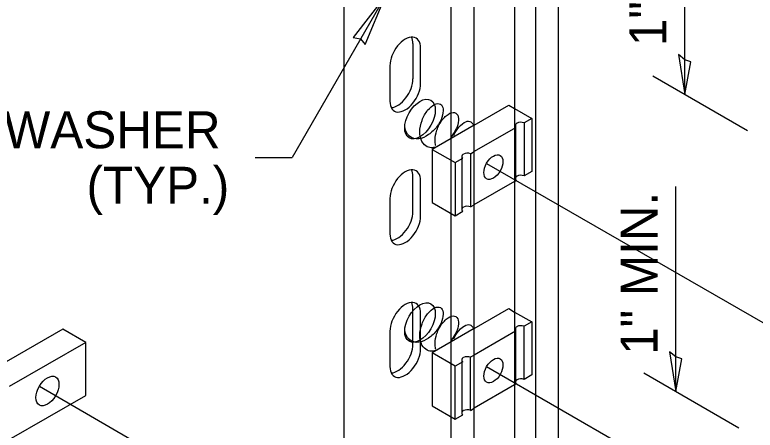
# Model space of a CAD drawing. Extents: x 99862 to 103151, y 100000 to 102076.
# Drawn here: x 101759.1 to 102079.7, y 100510.9 to 100690.6 of the extents above; entities that cross this region are included whole.
import ezdxf

# ---------------------------------------------------------------- set-up
doc = ezdxf.new("R2010")
doc.units = 0
for name, color, linetype in [('Level 1', 7, 'Continuous'), ('Level 15', 7, 'Continuous'), ('Level 16', 7, 'Continuous'), ('Level 20', 7, 'Continuous'), ('Level 3', 7, 'Continuous'), ('Level 7', 7, 'Continuous'), ('Level 8', 7, 'Continuous')]:
    doc.layers.add(name, color=color, linetype=linetype)

msp = doc.modelspace()

# ---------------------------------------------------------------- linework, layer by layer
at = {"layer": 'Level 1'}
for p, q in [((101901.65, 100836.31), (101901.65, 100346.41)), ((101975.53, 100836.31), (101975.53, 100342.05)), ((101994.46, 100342.6), (101994.46, 100836.31)), ((101984.51, 100830.57), (101984.51, 100336.86)), ((101958, 100325.36), (101958, 100815.26)), ((101948.05, 100319.62), (101948.05, 100809.52)), ((101931.48, 100678.14), (101931.48, 100662.83)), ((101934.8, 100660.91), (101934.8, 100676.22)), ((101921.54, 100668.57), (101921.54, 100653.26)), ((101931.48, 100605.42), (101931.48, 100620.73)), ((101934.8, 100603.5), (101934.8, 100618.81)), ((101921.54, 100611.16), (101921.54, 100595.85)), ((101931.48, 100548.01), (101931.48, 100563.32)), ((101934.8, 100546.09), (101934.8, 100561.4)), ((101921.54, 100553.75), (101921.54, 100538.44))]:
    msp.add_line(p, q, dxfattribs=at)
for centre, major_axis, start_param, end_param in [((101928.17, 100672.39), (4.69, 8.12), 5.497787, 8.63938), ((101924.85, 100674.31), (-4.69, -8.12), 2.356194, 2.780226), ((101928.17, 100657.08), (4.69, 8.12), 2.356194, 5.497787), ((101924.85, 100659), (-4.69, -8.12), 0.361367, 2.356194), ((101928.17, 100614.98), (4.69, 8.12), 5.497787, 8.63938), ((101924.85, 100616.9), (-4.69, -8.12), 2.356194, 2.780226), ((101924.85, 100601.59), (-4.69, -8.12), 0.361367, 2.356194), ((101928.17, 100599.68), (4.69, 8.12), 2.356194, 5.497787), ((101928.17, 100557.57), (4.69, 8.12), 5.497787, 8.63938), ((101924.85, 100559.49), (-4.69, -8.12), 2.356194, 2.780226), ((101924.85, 100544.18), (-4.69, -8.12), 0.361367, 2.356194), ((101928.17, 100542.27), (4.69, 8.12), 2.356194, 5.497787)]:
    msp.add_ellipse(centre, major_axis=major_axis, ratio=0.57735, start_param=start_param, end_param=end_param, dxfattribs=at)
at = {"layer": 'Level 15'}
for p, q in [((102049.16, 100656.1), (102049.16, 100716.68)), ((101919.66, 100698.98), (101879.16, 100628.84)), ((102076.42, 100640.36), (102035.3, 100664.1)), ((101863.16, 100628.84), (101879.16, 100628.84)), ((102045.28, 100527.56), (102045.28, 100616.32)), ((102072.54, 100511.81), (102031.42, 100535.56))]:
    msp.add_line(p, q, dxfattribs=at)
for points in [[(101919.66, 100698.98), (101905.66, 100680.71), (101908.77, 100680.13), (101910.83, 100677.72)], [(102049.16, 100656.1), (102051.83, 100670.29), (102049.16, 100671.1), (102046.49, 100673.37)], [(102045.28, 100527.56), (102047.95, 100541.74), (102045.28, 100542.56), (102042.61, 100544.83)]]:
    msp.add_lwpolyline(points, close=True, dxfattribs=at)
at = {"layer": 'Level 16'}
for p, q in [((101963.34, 100626.27), (102083.04, 100557.41)), ((101963.42, 100538.38), (102084.58, 100468.49)), ((101769.77, 100529.86), (101819.79, 100500.99))]:
    msp.add_line(p, q, dxfattribs=at)
at = {"layer": 'Level 3'}
for p, q in [((101958, 100642.86), (101972.98, 100651.51)), ((101972.98, 100651.51), (101975.53, 100650.03)), ((101975.53, 100650.03), (101982.92, 100645.77)), ((101976.59, 100643.72), (101976.53, 100643.68)), ((101982.92, 100645.77), (101979.61, 100643.85)), ((101979.61, 100643.85), (101979.61, 100620.89)), ((101982.92, 100645.77), (101982.92, 100622.8)), ((101958, 100642.86), (101939.83, 100632.37)), ((101975.85, 100641.68), (101958, 100631.38)), ((101975.85, 100642.73), (101975.85, 100619.76)), ((101939.83, 100632.37), (101939.83, 100609.41)), ((101939.83, 100632.37), (101949.78, 100626.63)), ((101956.41, 100630.46), (101958, 100631.38)), ((101949.78, 100626.63), (101953.09, 100628.54)), ((101952.65, 100629.33), (101952.65, 100606.37)), ((101953.39, 100630.32), (101953.33, 100630.28)), ((101953.33, 100630.28), (101953.39, 100630.32)), ((101956.41, 100630.46), (101956.41, 100607.49)), ((101949.78, 100626.63), (101949.78, 100603.66)), ((101982.92, 100622.8), (101979.61, 100620.89)), ((101975.53, 100618.53), (101957.93, 100608.37)), ((101975.53, 100618.53), (101976.29, 100618.97)), ((101976.59, 100620.75), (101976.53, 100620.71)), ((101939.83, 100609.41), (101949.78, 100603.66)), ((101949.78, 100603.66), (101953.09, 100605.58)), ((101953.39, 100607.36), (101953.33, 100607.32)), ((101953.33, 100607.32), (101953.39, 100607.36)), ((101956.41, 100607.49), (101958, 100608.41)), ((101958, 100554.83), (101972.98, 100563.48)), ((101972.98, 100563.48), (101975.53, 100562)), ((101975.53, 100562), (101982.92, 100557.74)), ((101982.92, 100557.74), (101979.61, 100555.82)), ((101982.92, 100557.74), (101982.92, 100534.77)), ((101958, 100554.83), (101939.83, 100544.34)), ((101975.85, 100554.7), (101975.85, 100531.74)), ((101976.59, 100555.69), (101976.53, 100555.65)), ((101979.61, 100532.86), (101979.61, 100555.82)), ((101975.85, 100553.65), (101958, 100543.35)), ((101949.78, 100538.6), (101939.83, 100544.34)), ((101939.83, 100544.34), (101939.83, 100521.38)), ((101952.65, 100541.3), (101952.65, 100518.34)), ((101953.39, 100542.29), (101953.33, 100542.25)), ((101953.39, 100542.29), (101953.33, 100542.25)), ((101958, 100543.35), (101956.41, 100542.43)), ((101956.41, 100519.46), (101956.41, 100542.43)), ((101953.09, 100540.51), (101949.78, 100538.6)), ((101949.78, 100515.64), (101949.78, 100538.6)), ((101982.92, 100534.77), (101979.61, 100532.86)), ((101976.59, 100532.72), (101976.53, 100532.69)), ((101975.53, 100530.51), (101958, 100520.39)), ((101976.29, 100530.95), (101975.53, 100530.51)), ((101939.83, 100521.38), (101949.78, 100515.64)), ((101953.39, 100519.33), (101953.33, 100519.29)), ((101953.33, 100519.29), (101953.39, 100519.33)), ((101956.41, 100519.46), (101958, 100520.39)), ((101949.78, 100515.64), (101953.09, 100517.55))]:
    msp.add_line(p, q, dxfattribs=at)
for centre, start_param, end_param in [((101978.24, 100642.77), 4.082321, 5.497787), ((101978.17, 100642.73), 5.497787, 6.283185), ((101954.97, 100629.33), 5.497787, 6.913253), ((101955.04, 100629.37), 4.082321, 5.497787), ((101978.17, 100619.76), 5.497787, 6.913253), ((101978.24, 100619.8), 4.082321, 5.497787), ((101954.97, 100606.37), 5.497787, 6.913253), ((101955.04, 100606.41), 4.082321, 5.497787), ((101978.17, 100554.7), 5.497787, 6.283185), ((101978.24, 100554.74), 4.082321, 5.497787), ((101954.97, 100541.3), 5.497787, 6.913253), ((101955.04, 100541.34), 4.082321, 5.497787), ((101978.17, 100531.74), 5.497787, 6.913253), ((101978.24, 100531.77), 4.082321, 5.497787), ((101954.97, 100518.34), 5.497787, 6.913253), ((101955.04, 100518.38), 4.082321, 5.497787)]:
    msp.add_ellipse(centre, major_axis=(-2.33, 0), ratio=0.57735, start_param=start_param, end_param=end_param, dxfattribs=at)
for centre in [(101966.35, 100624.71), (101966.35, 100536.69)]:
    msp.add_ellipse(centre, major_axis=(2.93, 5.07), ratio=0.57735, dxfattribs=at)
at = {"layer": 'Level 7'}
for centre in [(101934.56, 100645.49), (101934.56, 100557.46)]:
    msp.add_ellipse(centre, major_axis=(4.69, 8.12), ratio=0.57735, dxfattribs=at)
for points in [[(101941.41, 100633.27), (101941.2, 100633.23), (101940.08, 100633.02), (101937.72, 100633.2), (101935.14, 100635.38), (101934.16, 100639.82), (101935.19, 100645.04), (101937.78, 100649.59), (101940.98, 100652.24), (101943.68, 100652.3), (101944.78, 100650.12), (101944.36, 100646.27), (101942.17, 100642.11), (101938.36, 100638.48), (101934, 100636.39), (101929.6, 100637.49), (101928.16, 100640.65), (101927.95, 100642.35)], [(101941.35, 100633.87), (101941.27, 100634.23), (101941.05, 100635.6), (101941.22, 100639.34), (101943.35, 100644.46), (101946.85, 100648), (101949.77, 100648.7), (101951.43, 100646.8), (101951.15, 100642.96), (101949.46, 100639.6), (101948.16, 100637.93), (101947.92, 100637.64)], [(101949.16, 100638.36), (101949.61, 100639.35), (101951.28, 100642.23), (101954.55, 100644.85), (101956.79, 100644.45), (101957.41, 100643.49), (101957.54, 100643.19)], [(101941.41, 100545.24), (101941.2, 100545.2), (101940.08, 100544.99), (101937.72, 100545.17), (101935.14, 100547.35), (101934.16, 100551.79), (101935.19, 100557.01), (101937.78, 100561.57), (101940.98, 100564.21), (101943.68, 100564.27), (101944.78, 100562.09), (101944.36, 100558.24), (101942.17, 100554.09), (101938.36, 100550.45), (101934, 100548.37), (101929.6, 100549.46), (101928.16, 100552.62), (101927.95, 100554.32)], [(101941.35, 100545.84), (101941.27, 100546.2), (101941.05, 100547.57), (101941.22, 100551.31), (101943.35, 100556.43), (101946.85, 100559.98), (101949.77, 100560.67), (101951.43, 100558.77), (101951.15, 100554.93), (101949.46, 100551.57), (101948.16, 100549.9), (101947.92, 100549.61)], [(101949.16, 100550.33), (101949.61, 100551.32), (101951.28, 100554.2), (101954.55, 100556.82), (101956.79, 100556.42), (101957.41, 100555.47), (101957.54, 100555.17)]]:
    msp.add_open_spline(points, degree=3, dxfattribs=at)
at = {"layer": 'Level 8'}
for p, q in [((101779.92, 100554.62), (101746.77, 100535.49)), ((101789.86, 100548.88), (101779.92, 100554.62)), ((101789.86, 100548.88), (101756.71, 100529.75)), ((101789.86, 100525.92), (101789.86, 100548.88)), ((101756.71, 100506.78), (101789.86, 100525.92))]:
    msp.add_line(p, q, dxfattribs=at)
msp.add_ellipse((101773.29, 100527.83), major_axis=(-3.52, -6.09), ratio=0.57735, dxfattribs=at)

# ---------------------------------------------------------------- texts
at = {"layer": 'Level 20'}
for s, p in [('1"', (102041.16, 100677.03)), ('1" MIN.', (102037.39, 100543.44))]:
    msp.add_text(s, height=16, rotation=90.0001, dxfattribs=at).set_placement(p)
for s, p in [('FLAT WASHER', (101696.07, 100632.84)), ('(TYP.)', (101790.19, 100608.84))]:
    msp.add_text(s, height=16, dxfattribs=at).set_placement(p)

doc.saveas('drawing.dxf')
